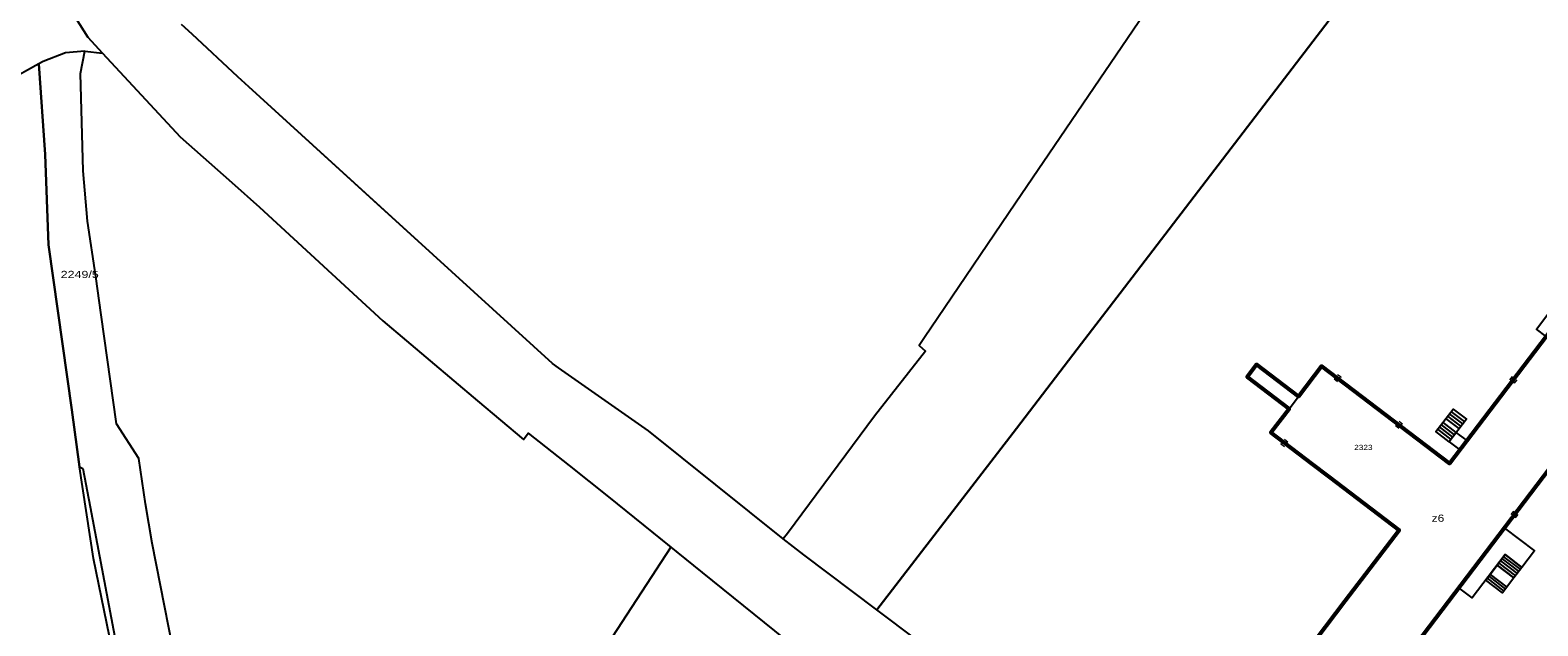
# Model space of a CAD drawing. Extents: x 4641351 to 4644672, y 5357112 to 5362385.
# Drawn here: x 4642629.6 to 4642892.9, y 5358688.2 to 5358792.2 of the extents above; entities that cross this region are included whole.
import ezdxf
from ezdxf.enums import TextEntityAlignment as Align

# ---------------------------------------------------------------- set-up
doc = ezdxf.new("R2010")
doc.units = 0
doc.header["$LTSCALE"] = 0.5
for name, color, linetype, lineweight in [('15', 7, 'Continuous', 25), ('16', 7, 'Continuous', 25), ('25', 7, 'Continuous', 25), ('27', 7, 'Continuous', 25), ('3', 7, 'Continuous', 13), ('6', 7, 'Continuous', 25)]:
    doc.layers.add(name, color=color, linetype=linetype, lineweight=lineweight)
doc.layers.add('24', color=7, linetype='Continuous')
doc.layers.add('4', color=7, linetype='Continuous')

msp = doc.modelspace()

# ---------------------------------------------------------------- linework, layer by layer
at = {"layer": '15'}
for p, q in [((4642880.059, 5358723.879), (4642877.737, 5358725.646)), ((4642877.994, 5358721.164), (4642875.671, 5358722.932)), ((4642878.302, 5358721.569), (4642875.979, 5358723.337)), ((4642878.61, 5358721.974), (4642876.287, 5358723.742)), ((4642879.115, 5358722.638), (4642876.792, 5358724.405)), ((4642879.43, 5358723.052), (4642877.107, 5358724.819)), ((4642879.744, 5358723.465), (4642877.422, 5358725.232)), ((4642877.686, 5358720.759), (4642875.363, 5358722.527)), ((4642886.036, 5358699.183), (4642888.956, 5358696.96)), ((4642886.315, 5358699.55), (4642889.235, 5358697.327)), ((4642886.594, 5358699.916), (4642889.514, 5358697.693)), ((4642886.873, 5358700.283), (4642889.793, 5358698.06)), ((4642884.008, 5358696.517), (4642886.928, 5358694.295)), ((4642884.27, 5358696.862), (4642887.19, 5358694.64)), ((4642884.532, 5358697.206), (4642887.452, 5358694.984))]:
    msp.add_line(p, q, dxfattribs=at)
for points in [[(4642894.301, 5358738.719), (4642892.589, 5358740.021), (4642896.878, 5358745.66), (4642898.59, 5358744.358)], [(4642877.378, 5358720.355), (4642875.056, 5358722.122), (4642878.052, 5358726.06), (4642880.374, 5358724.293)], [(4642880.481, 5358720.551), (4642878.61, 5358721.974), (4642877.378, 5358720.355), (4642879.249, 5358718.932)], [(4642890.072, 5358698.427), (4642888.676, 5358696.593), (4642885.756, 5358698.815), (4642887.152, 5358700.649)], [(4642888.676, 5358696.593), (4642886.666, 5358693.951), (4642883.746, 5358696.173), (4642885.756, 5358698.815)]]:
    msp.add_lwpolyline(points, close=True, dxfattribs=at)
at = {"layer": '16'}
msp.add_lwpolyline([(4642879.068, 5358694.858), (4642884.822, 5358702.421), (4642886.999, 5358705.276), (4642892.245, 5358701.282), (4642890.072, 5358698.427), (4642887.152, 5358700.649), (4642881.398, 5358693.085)], close=True, dxfattribs=at)
at = {"layer": '25'}
for points in [[(4642978.561, 5358810.056), (4642990.808, 5358823.689), (4643004.253, 5358810.143), (4643005.263, 5358807.882), (4643032.736, 5358821.848), (4643006.62, 5358847.88), (4642963.606, 5358890.762), (4642943.032, 5358907.228), (4642928.341, 5358888.023), (4642889.894, 5358837.761), (4642908.51, 5358823.77), (4642899.05, 5358811.62), (4642880.913, 5358826.022), (4642871.607, 5358813.853), (4642868.559, 5358809.868), (4642819.905, 5358746.262), (4642813.176, 5358737.465), (4642801.794, 5358722.681), (4642777.413, 5358691.01)], [(4642629.736, 5358806.664), (4642639.634, 5358790.956), (4642642.206, 5358788.176), (4642655.763, 5358773.534), (4642664.775, 5358765.559), (4642669.638, 5358761.256), (4642691.154, 5358741.466), (4642707.71, 5358727.471), (4642715.69, 5358720.725), (4642716.518, 5358721.854), (4642723.684, 5358716.172), (4642730.534, 5358710.741), (4642746.941, 5358697.518), (4642763.147, 5358684.457), (4642778.855, 5358671.797), (4642800.276, 5358656.176), (4642800.908, 5358655.63), (4642830.017, 5358633.306), (4642830.537, 5358632.906), (4642831.06, 5358632.485), (4642833.618, 5358630.427), (4642848.363, 5358618.565), (4642887.332, 5358588.823), (4642889.98, 5358586.54)], [(4642911.28, 5358587.64), (4642856.696, 5358630.545), (4642832.743, 5358648.89), (4642810.958, 5358666.108), (4642808.235, 5358668.12), (4642784.437, 5358685.7), (4642777.413, 5358691.01), (4642764.698, 5358700.623), (4642761.051, 5358703.38), (4642737.569, 5358722.223), (4642721.853, 5358733.265), (4642720.791, 5358734.011), (4642699.927, 5358752.949), (4642667.775, 5358782.265), (4642665.825, 5358784.043), (4642657.844, 5358791.471), (4642656.018, 5358793.17)], [(4642655.928, 5358676.933), (4642650.847, 5358702.647), (4642649.723, 5358709.537), (4642648.532, 5358717.394), (4642644.64, 5358723.444), (4642641.966, 5358742.511), (4642641.028, 5358749.196), (4642639.566, 5358758.814), (4642638.837, 5358767.621), (4642638.364, 5358784.632), (4642639.14, 5358788.515), (4642635.761, 5358788.201), (4642631.857, 5358786.716), (4642631.103, 5358786.296)], [(4642631.103, 5358786.296), (4642632.171, 5358770.448), (4642632.785, 5358754.713), (4642636.858, 5358725.887), (4642638.182, 5358715.974), (4642638.793, 5358715.688), (4642640.057, 5358708.989), (4642648.99, 5358661.629), (4642648.704, 5358661.278), (4642649.654, 5358658.622), (4642655.343, 5358642.709), (4642666.162, 5358610.308), (4642674.346, 5358591.121), (4642676.048, 5358586.826), (4642686.737, 5358562.504), (4642693.089, 5358550.679), (4642711.803, 5358527.418), (4642716.233, 5358522.576), (4642735.609, 5358502.997), (4642747.521, 5358490.039)]]:
    msp.add_lwpolyline(points, dxfattribs=at)
at = {"layer": '27'}
for points in [[(4642819.905, 5358746.262), (4642868.559, 5358809.868), (4642871.607, 5358813.853), (4642880.913, 5358826.022), (4642889.894, 5358837.761), (4642928.341, 5358888.023), (4642943.032, 5358907.228), (4642950.624, 5358917.154)], [(4642832.933, 5358808.039), (4642801.656, 5358761.97), (4642788.1, 5358741.99), (4642785.761, 5358738.556), (4642784.785, 5358737.118), (4642785.929, 5358736.168), (4642776.995, 5358724.815), (4642761.847, 5358704.333), (4642761.051, 5358703.38), (4642737.569, 5358722.223), (4642721.853, 5358733.265), (4642720.791, 5358734.011), (4642699.927, 5358752.949), (4642689.577, 5358762.379), (4642667.775, 5358782.265), (4642665.825, 5358784.043), (4642657.844, 5358791.471), (4642656.018, 5358793.17)], [(4642655.928, 5358676.933), (4642650.847, 5358702.647), (4642649.723, 5358709.537), (4642648.532, 5358717.394), (4642644.64, 5358723.444), (4642641.966, 5358742.511), (4642641.028, 5358749.196), (4642639.566, 5358758.814), (4642638.837, 5358767.621), (4642638.364, 5358784.632), (4642639.14, 5358788.515), (4642642.206, 5358788.176), (4642639.634, 5358790.956), (4642629.736, 5358806.664)], [(4642610.219, 5358691.154), (4642638.294, 5358666.158), (4642642.49, 5358665.804), (4642645.61, 5358667.889), (4642646.554, 5358669.818), (4642643.438, 5358686.334), (4642640.646, 5358699.982), (4642638.182, 5358715.974), (4642636.858, 5358725.887), (4642632.785, 5358754.713), (4642632.171, 5358770.448), (4642631.103, 5358786.296), (4642620.206, 5358780.25)], [(4642642.206, 5358788.176), (4642655.763, 5358773.534), (4642664.775, 5358765.559), (4642669.638, 5358761.256), (4642691.154, 5358741.466), (4642707.71, 5358727.471), (4642715.69, 5358720.725), (4642716.518, 5358721.854), (4642723.684, 5358716.172), (4642730.534, 5358710.741), (4642741.434, 5358701.951), (4642746.941, 5358697.518), (4642763.147, 5358684.457)], [(4642911.28, 5358587.64), (4642856.696, 5358630.545), (4642847.166, 5358637.845), (4642832.743, 5358648.89), (4642810.958, 5358666.108), (4642808.235, 5358668.12), (4642784.437, 5358685.7), (4642777.413, 5358691.01), (4642801.794, 5358722.681), (4642813.176, 5358737.465), (4642819.905, 5358746.262)], [(4642741.434, 5358701.951), (4642719.189, 5358667.889), (4642708.829, 5358673.949), (4642696.008, 5358652.217), (4642710.425, 5358640.715), (4642720.945, 5358632.132), (4642708.154, 5358614.737), (4642687.623, 5358587.332)]]:
    msp.add_lwpolyline(points, dxfattribs=at)
at = {"layer": '3'}
for p, q in [((4642858.486, 5358731.591), (4642857.284, 5358731.249)), ((4642857.881, 5358730.795), (4642857.284, 5358731.249)), ((4642858.486, 5358731.591), (4642857.889, 5358732.045)), ((4642888.375, 5358731.755), (4642887.921, 5358731.158)), ((4642888.375, 5358731.755), (4642888.717, 5358730.553)), ((4642889.171, 5358731.15), (4642888.717, 5358730.553)), ((4642869.205, 5358723.437), (4642868.003, 5358723.095)), ((4642868.6, 5358722.641), (4642868.003, 5358723.095)), ((4642869.205, 5358723.437), (4642868.608, 5358723.891)), ((4642847.983, 5358719.985), (4642849.185, 5358720.327)), ((4642848.588, 5358720.781), (4642849.185, 5358720.327)), ((4642847.983, 5358719.985), (4642848.58, 5358719.531)), ((4642888.176, 5358707.656), (4642888.63, 5358708.253)), ((4642888.972, 5358707.051), (4642888.63, 5358708.253)), ((4642888.972, 5358707.051), (4642889.426, 5358707.648))]:
    msp.add_line(p, q, dxfattribs=at)
at = {"layer": '3', "lineweight": 53}
msp.add_lwpolyline([(4642902.263, 5358749.186), (4642877.436, 5358716.548), (4642855.068, 5358733.563), (4642851.027, 5358728.251), (4642843.734, 5358733.832), (4642842.103, 5358731.701), (4642849.403, 5358726.116), (4642846.231, 5358721.946), (4642853.348, 5358716.532), (4642856.393, 5358714.216), (4642868.61, 5358704.922), (4642859.167, 5358692.51), (4642852.457, 5358683.687), (4642844.758, 5358673.567), (4642856.231, 5358664.839), (4642913.751, 5358740.447)], dxfattribs=at)
at = {"layer": '6'}
msp.add_line((4642849.403, 5358726.116), (4642851.027, 5358728.251), dxfattribs=at)

# ---------------------------------------------------------------- texts
at = {"layer": '24', "width": 1.3}
msp.add_text('2249/5', height=1.25, dxfattribs=at).set_placement((4642634.9, 5358748.918))
at = {"layer": '4', "width": 1.2}
msp.add_text('2323', height=0.9, dxfattribs=at).set_placement((4642860.774, 5358718.906))
at = {"layer": '4', "width": 1.25}
msp.add_text('z6', height=1.25, dxfattribs=at).set_placement((4642875.411, 5358706.385), align=Align.CENTER)

doc.saveas('drawing.dxf')
